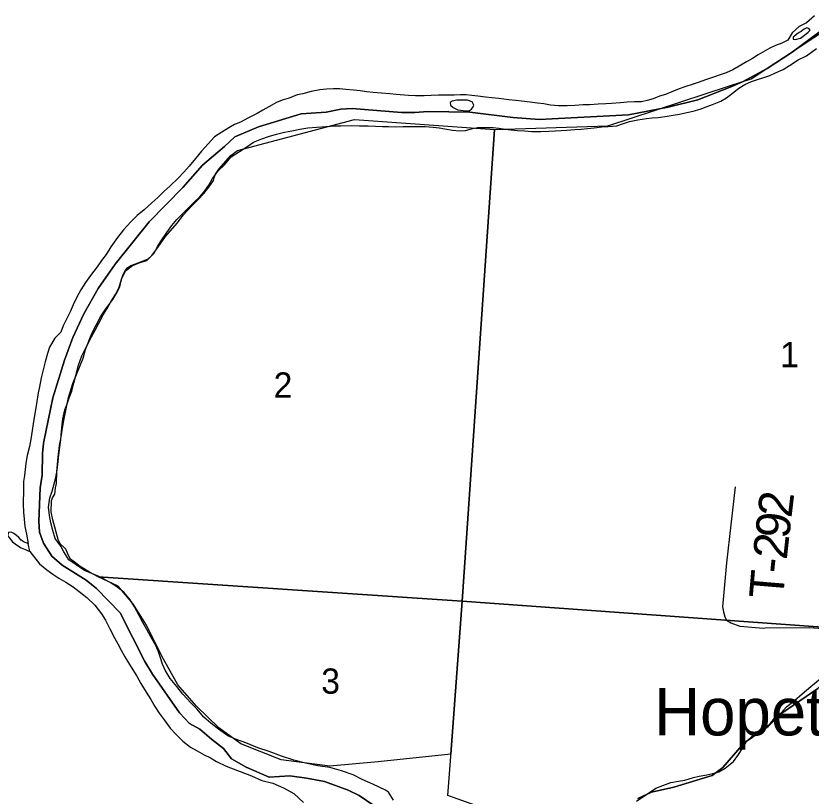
# Model space of a CAD drawing. Extents: x 0 to 34, y 0 to 22.
# Drawn here: x 3.839 to 5.16, y 17.231 to 18.527 of the extents above; entities that cross this region are included whole.
import ezdxf

# ---------------------------------------------------------------- set-up
doc = ezdxf.new("R2010")
doc.units = 0
for name, color, linetype in [('GM_X_Corporation', 7, 'Continuous'), ('GM_X_Major_River', 7, 'Continuous'), ('GM_X_Minor_River', 7, 'Continuous'), ('GM_X_Section_Text', 7, 'Continuous'), ('GM_X_Township_Road', 7, 'Continuous'), ('GM_X_Township_Road_Text', 7, 'Continuous'), ('GM_X_Unincorporated_Text', 7, 'Continuous')]:
    doc.layers.add(name, color=color, linetype=linetype)

msp = doc.modelspace()

# ---------------------------------------------------------------- linework, layer by layer
at = {"layer": 'GM_X_Corporation'}
for points in [[(5.1903, 18.5127), (5.1284, 18.4671), (5.0872, 18.4401), (5.046, 18.4176), (5.0254, 18.4087), (4.9721, 18.3878), (4.9226, 18.3753), (4.8565, 18.3629), (4.7091, 18.355), (4.6643, 18.3584), (4.593, 18.3673), (4.5231, 18.3686), (4.5018, 18.3665), (4.4798, 18.3667), (4.3979, 18.3735), (4.3789, 18.3721), (4.3545, 18.367), (4.3127, 18.3643), (4.2419, 18.3428), (4.2028, 18.3264), (4.1857, 18.31), (4.1491, 18.2792), (4.1163, 18.2422), (4.0606, 18.1849), (4.0041, 18.1147), (3.9758, 18.074), (3.9521, 18.0324), (3.9336, 17.993), (3.9197, 17.9552), (3.9004, 17.8923), (3.8847, 17.8172), (3.8831, 17.7998), (3.8828, 17.7641), (3.8797, 17.7429), (3.877, 17.6875), (3.8784, 17.6692), (3.8851, 17.651), (3.8986, 17.6296), (3.9159, 17.6143), (3.9558, 17.5897), (3.9732, 17.5759), (4.0122, 17.5353), (4.0533, 17.4546), (4.0661, 17.4332), (4.111, 17.3691), (4.1276, 17.3515), (4.1449, 17.3422), (4.1638, 17.3254), (4.1841, 17.3101), (4.1971, 17.2929), (4.2214, 17.2787), (4.26, 17.2624), (4.2942, 17.2646), (4.3216, 17.2603), (4.3516, 17.2552), (4.3911, 17.2406), (4.4091, 17.232), (4.4442, 17.208)], [(4.4442, 17.208), (4.4091, 17.232), (4.3911, 17.2406), (4.3516, 17.2552), (4.3216, 17.2603), (4.2942, 17.2646), (4.26, 17.2624), (4.2214, 17.2787), (4.1971, 17.2929), (4.1841, 17.3101), (4.1638, 17.3254), (4.1449, 17.3422), (4.1276, 17.3515), (4.111, 17.3691), (4.0661, 17.4332), (4.0533, 17.4546), (4.0122, 17.5353), (3.9732, 17.5759), (3.9558, 17.5897), (3.9159, 17.6143), (3.8986, 17.6296), (3.8851, 17.651), (3.8784, 17.6692), (3.877, 17.6875), (3.8797, 17.7429), (3.8828, 17.7641), (3.8831, 17.7998), (3.8847, 17.8172), (3.9004, 17.8923), (3.9197, 17.9552), (3.9336, 17.993), (3.9521, 18.0324), (3.9758, 18.074), (4.0041, 18.1147), (4.0606, 18.1849), (4.1163, 18.2422), (4.1491, 18.2792), (4.1857, 18.31), (4.2028, 18.3264), (4.2419, 18.3428), (4.3127, 18.3643), (4.3545, 18.367), (4.3789, 18.3721), (4.3979, 18.3735), (4.4798, 18.3667), (4.5018, 18.3665), (4.5231, 18.3686), (4.593, 18.3673), (4.6643, 18.3584), (4.7091, 18.355), (4.8565, 18.3629), (4.9226, 18.3753), (4.9721, 18.3878), (5.0254, 18.4087), (5.046, 18.4176), (5.0872, 18.4401), (5.1284, 18.4671), (5.1903, 18.5127)], [(5.3056, 17.2244), (5.3162, 17.2432), (5.3294, 17.2796), (5.3349, 17.3016), (5.3367, 17.3403), (5.3324, 17.3761), (5.3258, 17.3959), (5.2987, 17.4326), (5.2806, 17.4465), (5.2616, 17.4512), (5.2434, 17.4536), (5.2092, 17.441), (5.1886, 17.4297), (5.1709, 17.4094), (5.1114, 17.3688), (5.0884, 17.3462), (5.0487, 17.3191), (5.0135, 17.2784), (4.9959, 17.2648), (4.9319, 17.2456), (4.8947, 17.2375), (4.8723, 17.2265)], [(4.8723, 17.2265), (4.8947, 17.2375), (4.9319, 17.2456), (4.9959, 17.2648), (5.0135, 17.2784), (5.0487, 17.3191), (5.0884, 17.3462), (5.1114, 17.3688), (5.1709, 17.4094), (5.1886, 17.4297), (5.2092, 17.441), (5.2434, 17.4536), (5.2616, 17.4512), (5.2806, 17.4465), (5.2987, 17.4326), (5.3258, 17.3959), (5.3324, 17.3761), (5.3367, 17.3403), (5.3349, 17.3016), (5.3294, 17.2796), (5.3162, 17.2432), (5.3056, 17.2244)]]:
    msp.add_lwpolyline(points, dxfattribs=at)
for points in [[(5.1903, 18.5084), (5.6796, 18.4816), (5.601, 17.4809), (4.5805, 17.5547), (4.6339, 18.3385), (4.8225, 18.3445), (5.0229, 18.4102), (5.0604, 18.4225)], [(3.976, 17.5949), (3.9613, 17.6026), (3.9458, 17.6121), (3.936, 17.6198), (3.93, 17.6247), (3.9262, 17.6316), (3.9244, 17.6361), (3.9221, 17.6411), (3.9187, 17.6445), (3.9127, 17.6502), (3.9094, 17.6574), (3.9005, 17.6897), (3.8975, 17.7033), (3.898, 17.7215), (3.8999, 17.7261), (3.9038, 17.7325), (3.905, 17.7431), (3.9065, 17.7503), (3.907, 17.7696), (3.9091, 17.7938), (3.9115, 17.8131), (3.9138, 17.8244), (3.9173, 17.8456), (3.9185, 17.8551), (3.9205, 17.8634), (3.9217, 17.8687), (3.9232, 17.877), (3.9267, 17.8929), (3.9337, 17.9164), (3.951, 17.9583), (3.9545, 17.9731), (3.9653, 17.9995), (3.9798, 18.0274), (3.9875, 18.0388), (3.9951, 18.0493), (4.0001, 18.0561), (4.0058, 18.0652), (4.0116, 18.0772), (4.0128, 18.0822), (4.0139, 18.0871), (4.017, 18.0962), (4.0212, 18.1045), (4.0247, 18.1086), (4.03, 18.1124), (4.0421, 18.1168), (4.0547, 18.1217), (4.0588, 18.1235), (4.0649, 18.1292), (4.0749, 18.1424), (4.0875, 18.1605), (4.1077, 18.1835), (4.1172, 18.1959), (4.131, 18.211), (4.142, 18.2219), (4.1512, 18.2321), (4.1611, 18.2449), (4.1676, 18.2539), (4.1684, 18.2581), (4.1707, 18.2641), (4.1764, 18.2728), (4.1963, 18.2954), (4.2073, 18.3035), (4.4018, 18.3552), (4.6339, 18.3385), (4.5805, 17.5547)], [(3.976, 17.5949), (4.5805, 17.5547), (4.5617, 17.3002), (4.4407, 17.2877), (4.3608, 17.2802), (4.2798, 17.2908), (4.2127, 17.3175), (4.1764, 17.3441), (4.1391, 17.3804), (4.1082, 17.4155), (4.0816, 17.4635), (4.056, 17.5146), (4.0336, 17.5509), (4.0091, 17.5797)], [(4.5805, 17.5547), (5.601, 17.4809), (5.5235, 16.4744), (4.954, 16.5082), (5.0002, 16.5433), (5.2448, 16.7292), (5.1991, 16.9994), (4.9878, 17.1542), (4.7159, 17.1745), (4.6324, 17.2045), (4.5566, 17.2317), (4.5614, 17.2965), (4.5617, 17.3002)]]:
    msp.add_lwpolyline(points, close=True, dxfattribs=at)
at = {"layer": 'GM_X_Major_River'}
msp.add_line((3.8624, 17.6371), (3.8596, 17.6506), dxfattribs=at)
for points in [[(5.1658, 18.5272), (5.1521, 18.5159), (5.1403, 18.5094), (5.1285, 18.4992), (5.1213, 18.487), (5.1114, 18.4817), (5.1011, 18.4783), (5.0913, 18.4738), (5.0723, 18.4624), (5.0628, 18.4567), (5.0529, 18.4511), (5.0403, 18.4435), (5.0301, 18.4378), (5.0187, 18.4325), (5.0088, 18.4291), (4.9978, 18.4253), (4.9845, 18.4208), (4.9738, 18.417), (4.9643, 18.414), (4.9503, 18.4091), (4.9408, 18.406), (4.9286, 18.4011), (4.9179, 18.3966), (4.9081, 18.3936), (4.8974, 18.3894), (4.8879, 18.3864), (4.8784, 18.3845), (4.8667, 18.3845), (4.8545, 18.3838), (4.8431, 18.383), (4.8287, 18.3815), (4.8188, 18.3812)], [(5.1433, 18.5011), (5.1403, 18.4999), (5.1365, 18.4969), (5.1327, 18.4939), (5.1304, 18.492), (5.1304, 18.4885), (5.1338, 18.4878), (5.1422, 18.49), (5.149, 18.495), (5.1551, 18.5003), (5.1585, 18.5033), (5.1563, 18.5064), (5.1529, 18.5075), (5.1475, 18.5049)], [(5.1475, 18.5049), (5.1433, 18.5011)], [(4.8373, 18.3447), (4.8468, 18.3477), (4.8586, 18.3515), (4.8723, 18.3545), (4.8864, 18.3567), (4.8962, 18.3579), (4.9057, 18.3586), (4.9209, 18.3608), (4.9308, 18.3624), (4.9414, 18.3639), (4.9536, 18.3665), (4.9639, 18.3688), (4.9756, 18.3725), (4.9855, 18.3759), (4.9962, 18.3801), (5.0098, 18.3858), (5.0193, 18.3911), (5.0296, 18.399), (5.0399, 18.4074), (5.0501, 18.4134), (5.0608, 18.4184), (5.0707, 18.4214), (5.0813, 18.4248), (5.0912, 18.4282), (5.1007, 18.4324), (5.1136, 18.4384), (5.1243, 18.4449), (5.1387, 18.4543), (5.1524, 18.4611), (5.1691, 18.4733)], [(4.8188, 18.3812), (4.8063, 18.3804), (4.7922, 18.3797), (4.7812, 18.3793), (4.7675, 18.3782), (4.755, 18.3779), (4.7406, 18.3779), (4.7273, 18.3791), (4.7159, 18.381), (4.7056, 18.3821), (4.6931, 18.3837), (4.679, 18.3856), (4.6695, 18.3868), (4.6578, 18.3879), (4.6414, 18.3898), (4.6297, 18.391), (4.6194, 18.3922), (4.6065, 18.3941), (4.5966, 18.3952), (4.5871, 18.396), (4.5777, 18.396), (4.567, 18.3957), (4.5556, 18.3957), (4.5412, 18.3953), (4.529, 18.395), (4.5173, 18.3942), (4.5028, 18.3943), (4.4911, 18.3951), (4.4706, 18.3966), (4.4603, 18.3978), (4.4463, 18.3989), (4.4326, 18.4001), (4.4219, 18.4013), (4.4109, 18.4028), (4.3999, 18.404), (4.3874, 18.4051), (4.3771, 18.4059), (4.3669, 18.4063), (4.3551, 18.4056), (4.3437, 18.4041), (4.3297, 18.4014), (4.316, 18.398), (4.3061, 18.3958), (4.2932, 18.3908), (4.2814, 18.3874), (4.2719, 18.3833), (4.259, 18.3761), (4.2491, 18.3704), (4.2396, 18.3651), (4.2255, 18.3579), (4.2122, 18.3507), (4.2023, 18.3467)], [(4.5928, 18.3698), (4.5958, 18.3721), (4.5985, 18.3759), (4.5997, 18.3789), (4.597, 18.3842), (4.5894, 18.3873), (4.5799, 18.3873), (4.5716, 18.3873), (4.564, 18.3854), (4.5602, 18.3835), (4.5609, 18.379), (4.5655, 18.3752), (4.5734, 18.3713)], [(4.5734, 18.3713), (4.5865, 18.3693), (4.5928, 18.3698)], [(4.2023, 18.3467), (4.1928, 18.3411), (4.181, 18.334), (4.1692, 18.3262), (4.1585, 18.3149), (4.1474, 18.3025), (4.1374, 18.2901), (4.1271, 18.2776), (4.1183, 18.2675), (4.1087, 18.2577), (4.0946, 18.2442), (4.0846, 18.2352), (4.0751, 18.2254), (4.0648, 18.2168), (4.0522, 18.2051), (4.0403, 18.1954), (4.03, 18.1848), (4.0181, 18.1717), (4.0078, 18.1592), (3.997, 18.1434), (3.989, 18.1306), (3.9813, 18.1208), (3.974, 18.1102), (3.9629, 18.0956), (3.9549, 18.0842), (3.9472, 18.0722), (3.9402, 18.0597), (3.9341, 18.0473), (3.929, 18.0352), (3.9236, 18.0242), (3.9175, 18.0121), (3.9136, 18.0016), (3.904, 17.9918), (3.8952, 17.9767), (3.8917, 17.9661), (3.8878, 17.9525), (3.8846, 17.9389), (3.8811, 17.9256), (3.8783, 17.9109), (3.876, 17.9006), (3.8739, 17.8862), (3.8716, 17.8726), (3.8696, 17.8601), (3.8676, 17.8495), (3.866, 17.8385), (3.8639, 17.8241), (3.8619, 17.8116), (3.858, 17.7969), (3.8556, 17.784), (3.8544, 17.7734), (3.8536, 17.7635), (3.852, 17.7533), (3.8515, 17.7412), (3.8513, 17.7154), (3.8519, 17.7025), (3.8526, 17.6911), (3.854, 17.6789), (3.8565, 17.666), (3.8596, 17.6506)], [(4.1969, 18.2933), (4.2243, 18.3108), (4.2338, 18.3172), (4.2475, 18.3229), (4.2589, 18.3267), (4.2722, 18.3305), (4.2851, 18.3339), (4.2973, 18.3365), (4.3109, 18.3391), (4.3242, 18.341), (4.3539, 18.3432), (4.3694, 18.3443), (4.3789, 18.3447), (4.396, 18.3451), (4.4097, 18.3447), (4.4241, 18.3446), (4.4363, 18.3442), (4.4481, 18.3434), (4.4579, 18.3434), (4.4697, 18.343), (4.4822, 18.3434), (4.4963, 18.3437), (4.5081, 18.3437), (4.5187, 18.3433), (4.5324, 18.3422), (4.5422, 18.341), (4.5517, 18.3395), (4.5646, 18.3375), (4.576, 18.3364), (4.5859, 18.3367), (4.5958, 18.3394), (4.6057, 18.3416), (4.6216, 18.342), (4.6319, 18.342), (4.6414, 18.3404), (4.652, 18.3389), (4.6615, 18.3377), (4.6725, 18.337), (4.6839, 18.3362), (4.696, 18.3354), (4.7112, 18.335), (4.7245, 18.3357), (4.7348, 18.3361), (4.7447, 18.3368), (4.7542, 18.3376), (4.7675, 18.3383), (4.7781, 18.3391), (4.7883, 18.3402), (4.7997, 18.3413), (4.8123, 18.3428), (4.8229, 18.3432), (4.8373, 18.3447)], [(4.191, 17.3307), (4.1759, 17.3422), (4.1631, 17.3522), (4.1511, 17.3618), (4.1398, 17.3755), (4.1297, 17.3859), (4.1165, 17.4), (4.1064, 17.4126), (4.0952, 17.4264), (4.0869, 17.4401), (4.0828, 17.45), (4.0795, 17.4603), (4.0758, 17.4702), (4.0714, 17.4808), (4.0631, 17.4953), (4.0564, 17.5075), (4.0501, 17.5193), (4.0441, 17.5308), (4.0359, 17.5453), (4.0288, 17.5571), (4.0183, 17.5697), (4.0074, 17.5782), (3.9976, 17.5847), (3.9859, 17.5912), (3.9757, 17.5963), (3.9655, 17.6005), (3.953, 17.6056), (3.9395, 17.6148), (3.927, 17.6236), (3.9188, 17.6366), (3.914, 17.6461), (3.9042, 17.6588), (3.9005, 17.6721), (3.8972, 17.6846), (3.8951, 17.6968), (3.8933, 17.7108), (3.8953, 17.7264), (3.8992, 17.7373), (3.9027, 17.7498), (3.9055, 17.7604), (3.9075, 17.7725), (3.9091, 17.7865), (3.9107, 17.7979), (3.9123, 17.8108), (3.9136, 17.8229), (3.9148, 17.8369), (3.9161, 17.8475), (3.9169, 17.8578), (3.9204, 17.8725), (3.9243, 17.8824), (3.9278, 17.8926), (3.9321, 17.9039), (3.9356, 17.9168), (3.9388, 17.9296), (3.9431, 17.947), (3.9485, 17.9625), (3.9562, 17.978), (3.9647, 17.9939), (3.9709, 18.0052), (3.977, 18.0169), (3.984, 18.0305), (3.9909, 18.0411), (3.997, 18.052), (4.0047, 18.0641), (4.0105, 18.0765), (4.0144, 18.0898), (4.021, 18.1034), (4.0328, 18.1127), (4.0457, 18.1172), (4.0567, 18.1209), (4.0686, 18.1329), (4.0744, 18.1438), (4.0817, 18.1552), (4.0897, 18.1672), (4.0982, 18.1789), (4.1062, 18.1887), (4.1158, 18.1981), (4.1253, 18.2079), (4.1349, 18.2169), (4.1444, 18.2266), (4.1529, 18.2364), (4.1594, 18.2462), (4.1659, 18.2572), (4.1755, 18.2704), (4.1854, 18.2797), (4.1969, 18.2933)], [(3.8596, 17.6506), (3.8526, 17.6528), (3.8481, 17.6559), (3.844, 17.6604), (3.8402, 17.6639), (3.8357, 17.6673), (3.8312, 17.6693), (3.827, 17.6689), (3.8251, 17.664), (3.8333, 17.653), (3.8401, 17.6483), (3.848, 17.6433), (3.8533, 17.641), (3.8624, 17.6371)], [(3.8624, 17.6371), (3.8781, 17.6169), (3.8905, 17.6069), (3.9007, 17.5996), (3.9105, 17.5927), (3.9222, 17.5861), (3.9342, 17.5784), (3.9444, 17.5708), (3.9572, 17.5608), (3.9704, 17.5478), (3.9812, 17.5336), (3.988, 17.5233), (3.9954, 17.5088), (4.0029, 17.4936), (4.0085, 17.4837), (4.0137, 17.473), (4.02, 17.4623), (4.026, 17.452), (4.0331, 17.4406), (4.0402, 17.4299), (4.0466, 17.4181), (4.0555, 17.4036), (4.0634, 17.391), (4.0701, 17.3796), (4.0772, 17.3685), (4.0855, 17.3574), (4.0956, 17.3437), (4.105, 17.3334), (4.1166, 17.3219), (4.1294, 17.3123), (4.1404, 17.3057), (4.1517, 17.2995), (4.1622, 17.2941), (4.1724, 17.2884), (4.1883, 17.2806)], [(4.4666, 17.2238), (4.458, 17.2375), (4.4528, 17.2408), (4.4319, 17.2506), (4.4144, 17.2584), (4.3991, 17.2663), (4.3802, 17.2725), (4.3605, 17.278), (4.3408, 17.2812), (4.3203, 17.2852), (4.3006, 17.2906), (4.2801, 17.2969), (4.2597, 17.3047), (4.2408, 17.3109), (4.2211, 17.3194), (4.2037, 17.3256), (4.191, 17.3307)], [(4.1883, 17.2806), (4.2305, 17.2646), (4.2479, 17.2569), (4.2661, 17.2522), (4.2835, 17.2444), (4.3009, 17.2352), (4.3171, 17.2202)]]:
    msp.add_lwpolyline(points, dxfattribs=at)
at = {"layer": 'GM_X_Minor_River'}
msp.add_lwpolyline([(4.8701, 17.2225), (4.9023, 17.2437), (4.9137, 17.2486), (4.927, 17.2531), (4.9396, 17.2554), (4.9502, 17.2572), (4.9646, 17.2614), (4.9741, 17.264), (4.9867, 17.2663), (4.9966, 17.2682), (5.0068, 17.2712), (5.0171, 17.2769), (5.0308, 17.2883), (5.038, 17.2981), (5.0464, 17.3107), (5.0525, 17.3217), (5.0624, 17.3311), (5.0764, 17.3402), (5.0913, 17.3501), (5.0993, 17.3603), (5.1103, 17.3691), (5.119, 17.3789), (5.1323, 17.3895), (5.1453, 17.4005), (5.1594, 17.4131), (5.1753, 17.4256)], dxfattribs=at)
at = {"layer": 'GM_X_Township_Road'}
for points in [[(5.0338, 17.7444), (5.0194, 17.6184), (5.0128, 17.5455), (5.0142, 17.5367), (5.0167, 17.5287), (5.0196, 17.5233), (5.0267, 17.5186), (5.0418, 17.513), (5.0807, 17.51), (5.0838, 17.5101)], [(5.0838, 17.5101), (5.1575, 17.5108), (5.5249, 17.4823), (5.5253, 17.4823), (5.539, 17.4813)]]:
    msp.add_lwpolyline(points, dxfattribs=at)

# ---------------------------------------------------------------- texts
at = {"layer": 'GM_X_Section_Text'}
for s, p in [('1', (5.1084, 17.9434)), ('2', (4.2672, 17.8929)), ('3', (4.3463, 17.4009))]:
    msp.add_text(s, height=0.0419, rotation=0, dxfattribs=at).set_placement(p)
at = {"layer": 'GM_X_Township_Road_Text'}
for s, rotation, p in [('2', 83.2713, (5.1272, 17.6919)), ('9', 83.3552, (5.1232, 17.6571)), ('2', 83.6851, (5.1194, 17.6224)), ('-', 84.0727, (5.117, 17.5993)), ('T', 85.1687, (5.1134, 17.5572))]:
    msp.add_text(s, height=0.0568, rotation=rotation, dxfattribs=at).set_placement(p)
at = {"layer": 'GM_X_Unincorporated_Text'}
msp.add_text('Hopetown', height=0.07898, rotation=0, dxfattribs=at).set_placement((4.8993, 17.3316))

doc.saveas('drawing.dxf')
